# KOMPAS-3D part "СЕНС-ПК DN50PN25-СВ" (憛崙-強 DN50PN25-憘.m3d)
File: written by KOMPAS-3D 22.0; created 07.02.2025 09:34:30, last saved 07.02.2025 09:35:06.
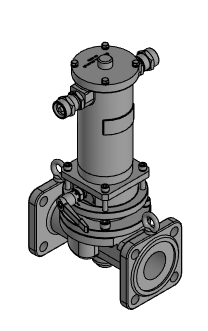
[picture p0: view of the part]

Document properties: Автор: setup; Полное имя файла: \\10.10.77.77\!! users\Савин А.Г\!Клапаны 3D для заказчика\СЕНС-ПК\1. СЕНС-ПК\СЕНС-ПК DN50PN25-СВ.m3d

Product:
- Body: Тело 3
    Масса: 17.833746
- Part/product: СЕНС-ПК DN50PN25-СВ
    Масса: 17.612808

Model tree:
1. Операция без истории:1
2. Эскиз:1  (with: Операция без истории:1)
3. Элемент выдавливания:1
     Расстояние 1 = 14
4. Фаска:1  (with: Элемент выдавливания:1)
     Угол = 45; Длина 1 = 2; Длина 2 = 2

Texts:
  Body Specification ( left align )
  Body Specificaton ( centered )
